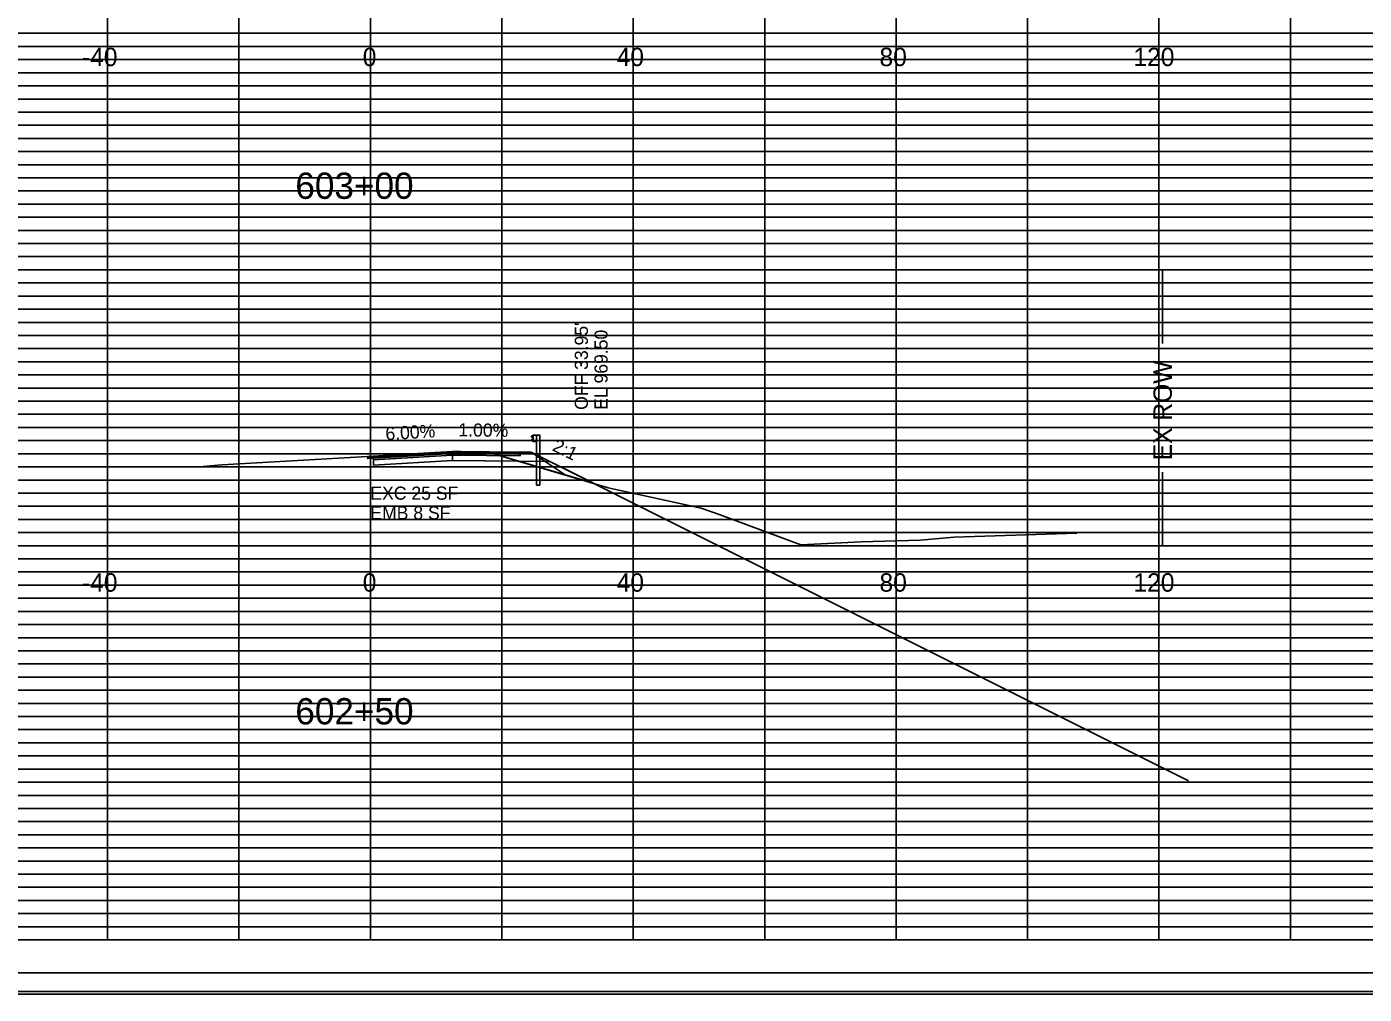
# Model space of a CAD drawing. Extents: x 2313580 to 2322968, y 282099 to 303247.
# Drawn here: x 2318731.4 to 2318934.9, y 287579.4 to 287726.7 of the extents above; entities that cross this region are included whole.
import ezdxf

# ---------------------------------------------------------------- set-up
doc = ezdxf.new("R2010")
doc.units = 0
for name, color, linetype in [('DESIGN - CENTERLINE - Proposed', 7, 'Continuous'), ('DESIGN - DRAINAGE - Text', 7, 'Continuous'), ('DESIGN - EARTHWORK - Excavation Limit Lines', 7, 'Continuous'), ('DESIGN - EARTHWORK - Shapes', 7, 'Continuous'), ('DESIGN - SCRATCH - User 1', 7, 'Continuous'), ('DESIGN - SHEET - Light Grid', 7, 'Continuous'), ('DESIGN - SHEET - Linework', 7, 'Continuous'), ('DESIGN - SHEET - Plot Shape', 7, 'Continuous'), ('DESIGN - TYPICAL - Finished Grade and Subgrade', 7, 'Continuous'), ('DESIGN - TYPICAL - Finished Grade Slopes Text', 7, 'Continuous'), ('DESIGN - TYPICAL - Guardrail', 7, 'Continuous'), ('DESIGN - TYPICAL - Text', 7, 'Continuous'), ('Scratch Level', 7, 'Continuous'), ('SURVEY - GROUND - Top of Ground', 7, 'Continuous'), ('SURVEY - PROPERTY - ROW Lines Text', 7, 'Continuous')]:
    doc.layers.add(name, color=color, linetype=linetype)

# ---------------------------------------------------------------- blocks, each defined once
blk = doc.blocks.new('GRTYP')
at = {"layer": 'DESIGN - CENTERLINE - Proposed'}
for p, q in [((0.162, 0.37), (0.162, 0.37)), ((0.162, 0.37), (0.162, 0.37)), ((0.264, 0.37), (0.264, 0.37)), ((0.264, 0.37), (0.264, 0.37))]:
    blk.add_line(p, q, dxfattribs=at)
for points in [[(0.059, 0.567), (0.04, 0.563), (0.004, 0.539), (0, 0.531), (0.004, 0.523), (0.055, 0.492), (0.059, 0.484), (0.059, 0.464), (0.055, 0.456), (0.004, 0.425), (0, 0.417), (0.004, 0.409), (0.04, 0.385), (0.059, 0.382)], [(0.162, 0.374), (0.059, 0.374), (0.059, 0.574), (0.162, 0.574)], [(0.264, -0.126), (0.264, 0.574), (0.162, 0.574), (0.162, -0.075)], [(0.162, -0.075), (0.162, -0.949), (0.264, -0.949), (0.264, -0.122)]]:
    blk.add_lwpolyline(points, dxfattribs=at)

msp = doc.modelspace()

# ---------------------------------------------------------------- linework, layer by layer
at = {"layer": 'DESIGN - EARTHWORK - Shapes'}
for points in [[(2318783.28, 287661.25), (2318789.34, 287661.6), (2318791.77, 287661.74), (2318802.17, 287661.67), (2318802.34, 287661.66), (2318802.59, 287661.61), (2318802.93, 287661.51), (2318806.25, 287660.53), (2318796.16, 287660.63), (2318784.16, 287659.91), (2318784.16, 287660.74), (2318784.16, 287660.99), (2318783.28, 287660.94), (2318783.28, 287661.15)], [(2318806.25, 287660.53), (2318817.63, 287657.17), (2318811, 287660.48), (2318810.27, 287660.49)]]:
    msp.add_lwpolyline(points, close=True, dxfattribs=at)
at = {"layer": 'DESIGN - SCRATCH - User 1'}
msp.add_line((2318808.16, 287661.9), (2318908.16, 287611.9), dxfattribs=at)
msp.add_lwpolyline([(2318806.16, 287661.92), (2318808.16, 287661.9), (2318813.31, 287658.45)], dxfattribs=at)
msp.add_lwpolyline([(2318806.16, 287661.92), (2318808.16, 287661.9), (2318813.31, 287658.45)], dxfattribs=at)
msp.add_lwpolyline([(2318806.16, 287661.92), (2318808.16, 287661.9), (2318813.31, 287658.45)], dxfattribs=at)
msp.add_lwpolyline([(2318806.16, 287661.92), (2318808.16, 287661.9), (2318813.31, 287658.45)], dxfattribs=at)
at = {"layer": 'DESIGN - SHEET - Light Grid'}
for p, q in [((2318623.68, 287725.67), (2318783.68, 287725.67)), ((2318783.68, 287725.67), (2318943.68, 287725.67)), ((2318623.68, 287723.67), (2318783.68, 287723.67)), ((2318783.68, 287723.67), (2318943.68, 287723.67)), ((2318623.68, 287721.67), (2318783.68, 287721.67)), ((2318783.68, 287721.67), (2318943.68, 287721.67)), ((2318623.68, 287719.67), (2318783.68, 287719.67)), ((2318783.68, 287719.67), (2318943.68, 287719.67)), ((2318623.68, 287717.67), (2318783.68, 287717.67)), ((2318783.68, 287717.67), (2318943.68, 287717.67)), ((2318623.68, 287715.67), (2318783.68, 287715.67)), ((2318783.68, 287715.67), (2318943.68, 287715.67)), ((2318623.68, 287713.67), (2318783.68, 287713.67)), ((2318783.68, 287713.67), (2318943.68, 287713.67)), ((2318623.68, 287711.67), (2318783.68, 287711.67)), ((2318783.68, 287711.67), (2318943.68, 287711.67)), ((2318623.68, 287709.67), (2318783.68, 287709.67)), ((2318783.68, 287709.67), (2318943.68, 287709.67)), ((2318623.68, 287705.67), (2318783.68, 287705.67)), ((2318783.68, 287705.67), (2318943.68, 287705.67)), ((2318623.68, 287703.67), (2318783.68, 287703.67)), ((2318783.68, 287703.67), (2318943.68, 287703.67)), ((2318623.68, 287701.67), (2318783.68, 287701.67)), ((2318783.68, 287701.67), (2318943.68, 287701.67)), ((2318623.68, 287699.67), (2318783.68, 287699.67)), ((2318623.68, 287697.67), (2318783.68, 287697.67)), ((2318783.68, 287699.67), (2318943.68, 287699.67)), ((2318783.68, 287697.67), (2318943.68, 287697.67)), ((2318623.68, 287695.67), (2318783.68, 287695.67)), ((2318783.68, 287695.67), (2318943.68, 287695.67)), ((2318623.68, 287693.67), (2318783.68, 287693.67)), ((2318783.68, 287693.67), (2318943.68, 287693.67)), ((2318623.68, 287691.67), (2318783.68, 287691.67)), ((2318783.68, 287691.67), (2318943.68, 287691.67)), ((2318623.68, 287689.67), (2318783.68, 287689.67)), ((2318783.68, 287689.67), (2318943.68, 287689.67)), ((2318623.68, 287685.67), (2318783.68, 287685.67)), ((2318783.68, 287685.67), (2318943.68, 287685.67)), ((2318623.68, 287683.67), (2318783.68, 287683.67)), ((2318783.68, 287683.67), (2318943.68, 287683.67)), ((2318623.68, 287681.67), (2318783.68, 287681.67)), ((2318783.68, 287681.67), (2318943.68, 287681.67)), ((2318623.68, 287679.67), (2318783.68, 287679.67)), ((2318783.68, 287679.67), (2318943.68, 287679.67)), ((2318623.68, 287677.67), (2318783.68, 287677.67)), ((2318783.68, 287677.67), (2318943.68, 287677.67)), ((2318623.68, 287675.67), (2318783.68, 287675.67)), ((2318783.68, 287675.67), (2318943.68, 287675.67)), ((2318623.68, 287673.67), (2318783.68, 287673.67)), ((2318783.68, 287673.67), (2318943.68, 287673.67)), ((2318623.68, 287671.67), (2318783.68, 287671.67)), ((2318783.68, 287671.67), (2318943.68, 287671.67)), ((2318623.68, 287669.67), (2318783.68, 287669.67)), ((2318783.68, 287669.67), (2318943.68, 287669.67)), ((2318623.68, 287665.67), (2318783.68, 287665.67)), ((2318783.68, 287665.67), (2318943.68, 287665.67)), ((2318623.68, 287663.67), (2318783.68, 287663.67)), ((2318783.68, 287663.67), (2318943.68, 287663.67)), ((2318623.68, 287661.67), (2318783.68, 287661.67)), ((2318783.68, 287661.67), (2318943.68, 287661.67)), ((2318623.68, 287659.67), (2318783.68, 287659.67)), ((2318783.68, 287659.67), (2318943.68, 287659.67)), ((2318623.68, 287657.67), (2318783.68, 287657.67)), ((2318783.68, 287657.67), (2318943.68, 287657.67)), ((2318623.68, 287655.67), (2318783.68, 287655.67)), ((2318783.68, 287655.67), (2318943.68, 287655.67)), ((2318623.68, 287653.67), (2318783.68, 287653.67)), ((2318783.68, 287653.67), (2318943.68, 287653.67)), ((2318623.68, 287651.67), (2318783.68, 287651.67)), ((2318783.68, 287651.67), (2318943.68, 287651.67)), ((2318623.68, 287649.67), (2318783.68, 287649.67)), ((2318783.68, 287649.67), (2318943.68, 287649.67)), ((2318623.68, 287645.67), (2318783.68, 287645.67)), ((2318783.68, 287645.67), (2318943.68, 287645.67)), ((2318623.68, 287643.67), (2318783.68, 287643.67)), ((2318783.68, 287643.67), (2318943.68, 287643.67)), ((2318623.68, 287641.67), (2318783.68, 287641.67)), ((2318783.68, 287641.67), (2318943.68, 287641.67)), ((2318623.68, 287639.67), (2318783.68, 287639.67)), ((2318783.68, 287639.67), (2318943.68, 287639.67)), ((2318623.68, 287637.67), (2318783.68, 287637.67)), ((2318783.68, 287637.67), (2318943.68, 287637.67)), ((2318623.68, 287635.67), (2318783.68, 287635.67)), ((2318783.68, 287635.67), (2318943.68, 287635.67)), ((2318623.68, 287633.67), (2318783.68, 287633.67)), ((2318783.68, 287633.67), (2318943.68, 287633.67)), ((2318623.68, 287631.67), (2318783.68, 287631.67)), ((2318783.68, 287631.67), (2318943.68, 287631.67)), ((2318623.68, 287629.67), (2318783.68, 287629.67)), ((2318783.68, 287629.67), (2318943.68, 287629.67)), ((2318623.68, 287625.67), (2318783.68, 287625.67)), ((2318783.68, 287625.67), (2318943.68, 287625.67)), ((2318623.68, 287623.67), (2318783.68, 287623.67)), ((2318783.68, 287623.67), (2318943.68, 287623.67)), ((2318623.68, 287621.67), (2318783.68, 287621.67)), ((2318783.68, 287621.67), (2318943.68, 287621.67)), ((2318623.68, 287619.67), (2318783.68, 287619.67)), ((2318783.68, 287619.67), (2318943.68, 287619.67)), ((2318623.68, 287617.67), (2318783.68, 287617.67)), ((2318783.68, 287617.67), (2318943.68, 287617.67)), ((2318623.68, 287615.67), (2318783.68, 287615.67)), ((2318783.68, 287615.67), (2318943.68, 287615.67)), ((2318623.68, 287613.67), (2318783.68, 287613.67)), ((2318783.68, 287613.67), (2318943.68, 287613.67)), ((2318623.68, 287611.67), (2318783.68, 287611.67)), ((2318783.68, 287611.67), (2318943.68, 287611.67)), ((2318623.68, 287609.67), (2318783.68, 287609.67)), ((2318783.68, 287609.67), (2318943.68, 287609.67)), ((2318623.68, 287605.67), (2318783.68, 287605.67)), ((2318783.68, 287605.67), (2318943.68, 287605.67)), ((2318623.68, 287603.67), (2318783.68, 287603.67)), ((2318783.68, 287603.67), (2318943.68, 287603.67)), ((2318623.68, 287601.67), (2318783.68, 287601.67)), ((2318783.68, 287601.67), (2318943.68, 287601.67)), ((2318623.68, 287599.67), (2318783.68, 287599.67)), ((2318783.68, 287599.67), (2318943.68, 287599.67)), ((2318623.68, 287597.67), (2318783.68, 287597.67)), ((2318783.68, 287597.67), (2318943.68, 287597.67)), ((2318623.68, 287595.67), (2318783.68, 287595.67)), ((2318783.68, 287595.67), (2318943.68, 287595.67)), ((2318623.68, 287593.67), (2318783.68, 287593.67)), ((2318783.68, 287593.67), (2318943.68, 287593.67)), ((2318623.68, 287591.67), (2318783.68, 287591.67)), ((2318783.68, 287591.67), (2318943.68, 287591.67)), ((2318623.68, 287589.67), (2318783.68, 287589.67)), ((2318783.68, 287589.67), (2318943.68, 287589.67))]:
    msp.add_line(p, q, dxfattribs=at)
at = {"layer": 'DESIGN - SHEET - Linework'}
for p, q in [((2318743.68, 287587.67), (2318743.68, 288007.67)), ((2318763.68, 287587.67), (2318763.68, 288007.67)), ((2318783.68, 287587.67), (2318783.68, 288007.67)), ((2318803.68, 287587.67), (2318803.68, 288007.67)), ((2318823.68, 287587.67), (2318823.68, 288007.67)), ((2318843.68, 287587.67), (2318843.68, 288007.67)), ((2318863.68, 287587.67), (2318863.68, 288007.67)), ((2318883.68, 287587.67), (2318883.68, 288007.67)), ((2318903.68, 287587.67), (2318903.68, 288007.67)), ((2318923.68, 287587.67), (2318923.68, 288007.67)), ((2318463.68, 287707.67), (2319103.68, 287707.67)), ((2318463.68, 287687.67), (2319103.68, 287687.67)), ((2318463.68, 287667.67), (2319103.68, 287667.67)), ((2318463.68, 287647.67), (2319103.68, 287647.67)), ((2318463.68, 287627.67), (2319103.68, 287627.67)), ((2318463.68, 287607.67), (2319103.68, 287607.67)), ((2318427.22, 287579.39), (2319108.02, 287579.39))]:
    msp.add_line(p, q, dxfattribs=at)
msp.add_lwpolyline([(2318463.68, 288007.67), (2318463.68, 287587.67), (2319103.68, 287587.67), (2319103.68, 288007.67), (2318463.68, 288007.67)], dxfattribs=at)
at = {"layer": 'DESIGN - SHEET - Plot Shape'}
for points in [[(2318427.62, 288015.55), (2319107.62, 288015.55), (2319107.62, 287579.79), (2318427.62, 287579.79)], [(2318446.68, 288007.67), (2319103.68, 288007.67), (2319103.68, 287582.67), (2318446.68, 287582.67)]]:
    msp.add_lwpolyline(points, close=True, dxfattribs=at)
at = {"layer": 'DESIGN - TYPICAL - Finished Grade and Subgrade'}
msp.add_lwpolyline([(2318783.28, 287661.25), (2318783.39, 287661.26), (2318784.16, 287661.3), (2318785.63, 287661.39), (2318796.16, 287662.02), (2318797.39, 287662.01), (2318806.16, 287661.92), (2318806.41, 287661.92), (2318808.16, 287661.9), (2318817.63, 287657.17)], dxfattribs=at)
for points in [[(2318784.16, 287661.3), (2318783.28, 287661.25), (2318783.28, 287661.15), (2318784.16, 287661.2)], [(2318784.16, 287661.2), (2318784.16, 287660.99), (2318783.28, 287660.94), (2318783.28, 287661.15)], [(2318784.16, 287661.3), (2318796.16, 287662.02), (2318796.16, 287661.92), (2318784.16, 287661.2)], [(2318784.16, 287661.2), (2318796.16, 287661.92), (2318796.16, 287661.71), (2318784.16, 287660.99)], [(2318784.16, 287660.99), (2318796.16, 287661.71), (2318796.16, 287661.46), (2318784.16, 287660.74)], [(2318784.16, 287660.74), (2318796.16, 287661.46), (2318796.16, 287660.63), (2318784.16, 287659.91)], [(2318796.16, 287662.02), (2318806.16, 287661.92), (2318806.16, 287661.82), (2318796.16, 287661.92)], [(2318796.16, 287661.46), (2318806.48, 287661.37), (2318806.48, 287661.62), (2318806.27, 287661.62), (2318806.27, 287661.82), (2318806.16, 287661.82), (2318806.16, 287661.92), (2318808.16, 287661.9), (2318811, 287660.48), (2318796.16, 287660.63)], [(2318796.16, 287661.92), (2318806.27, 287661.82), (2318806.27, 287661.62), (2318796.16, 287661.71)], [(2318796.16, 287661.71), (2318806.48, 287661.62), (2318806.48, 287661.37), (2318796.16, 287661.46)], [(2318796.16, 287661.71), (2318806.48, 287661.62), (2318806.48, 287661.37), (2318796.16, 287661.46)]]:
    msp.add_lwpolyline(points, close=True, dxfattribs=at)
at = {"layer": 'Scratch Level'}
for points in [[(2318783.28, 287661.25), (2318789.34, 287661.6), (2318791.77, 287661.74), (2318802.17, 287661.67), (2318802.34, 287661.66), (2318802.59, 287661.61), (2318802.93, 287661.51), (2318806.25, 287660.53), (2318796.16, 287660.63), (2318784.16, 287659.91), (2318784.16, 287660.74), (2318784.16, 287660.99), (2318783.28, 287660.94), (2318783.28, 287661.15)], [(2318806.25, 287660.53), (2318817.63, 287657.17), (2318811, 287660.48), (2318810.27, 287660.49)]]:
    msp.add_lwpolyline(points, close=True, dxfattribs=at)
at = {"layer": 'SURVEY - GROUND - Top of Ground'}
msp.add_lwpolyline([(2318757.42, 287659.68), (2318757.68, 287659.68), (2318760.49, 287659.92), (2318761.06, 287659.97), (2318780.63, 287661.09), (2318789.34, 287661.6), (2318791.77, 287661.74), (2318802.17, 287661.67), (2318802.34, 287661.66), (2318802.59, 287661.61), (2318802.93, 287661.51), (2318819.89, 287656.5), (2318834.04, 287653.4), (2318836.89, 287652.35), (2318849.2, 287647.82), (2318858.37, 287648.26), (2318867.36, 287648.49), (2318872.49, 287648.95), (2318891.18, 287649.6)], dxfattribs=at)
at = {"layer": 'SURVEY - PROPERTY - ROW Lines Text'}
for p, q in [((2318904.24, 287689.67), (2318904.24, 287678.47)), ((2318904.24, 287647.67), (2318904.24, 287658.87))]:
    msp.add_line(p, q, dxfattribs=at)

# ---------------------------------------------------------------- block references
at = {"layer": 'DESIGN - TYPICAL - Guardrail', "xscale": 5, "yscale": 5}
msp.add_blockref('GRTYP', (2318808.16, 287661.65), dxfattribs=at)

# ---------------------------------------------------------------- texts
at = {"layer": 'DESIGN - DRAINAGE - Text'}
for s, p in [("OFF 33.95'", (2318816.78, 287668.35)), ('EL 969.50', (2318819.78, 287668.35))]:
    msp.add_text(s, height=2, rotation=90, dxfattribs=at).set_placement(p)
at = {"layer": 'DESIGN - EARTHWORK - Excavation Limit Lines'}
for s, p in [('EXC 25 SF', (2318783.68, 287654.67)), ('EMB 8 SF', (2318783.68, 287651.67))]:
    msp.add_text(s, height=2, dxfattribs=at).set_placement(p)
at = {"layer": 'DESIGN - TYPICAL - Finished Grade Slopes Text'}
for s, rotation, p in [('6.00%', 3.434, (2318786.03, 287663.72)), ('1.00%', 359.4275, (2318797.07, 287664.31)), ('2:1', 333.8029, (2318811.23, 287662.22))]:
    msp.add_text(s, height=2, rotation=rotation, dxfattribs=at).set_placement(p)
at = {"layer": 'DESIGN - TYPICAL - Text'}
for s, height, p in [('-40', 2.8, (2318739.79, 287720.67)), ('0', 2.8, (2318782.52, 287720.67)), ('40', 2.8, (2318821.15, 287720.67)), ('80', 2.8, (2318861.15, 287720.67)), ('120', 2.8, (2318899.79, 287720.67)), ('603+00', 4, (2318772.26, 287700.47)), ('-40', 2.8, (2318739.79, 287640.67)), ('0', 2.8, (2318782.52, 287640.67)), ('40', 2.8, (2318821.15, 287640.67)), ('80', 2.8, (2318861.15, 287640.67)), ('120', 2.8, (2318899.79, 287640.67)), ('602+50', 4, (2318772.26, 287620.47))]:
    msp.add_text(s, height=height, dxfattribs=at).set_placement(p)
at = {"layer": 'SURVEY - PROPERTY - ROW Lines Text'}
msp.add_text('EX ROW', height=2.8, rotation=90, dxfattribs=at).set_placement((2318905.64, 287660.67))

doc.saveas('drawing.dxf')
